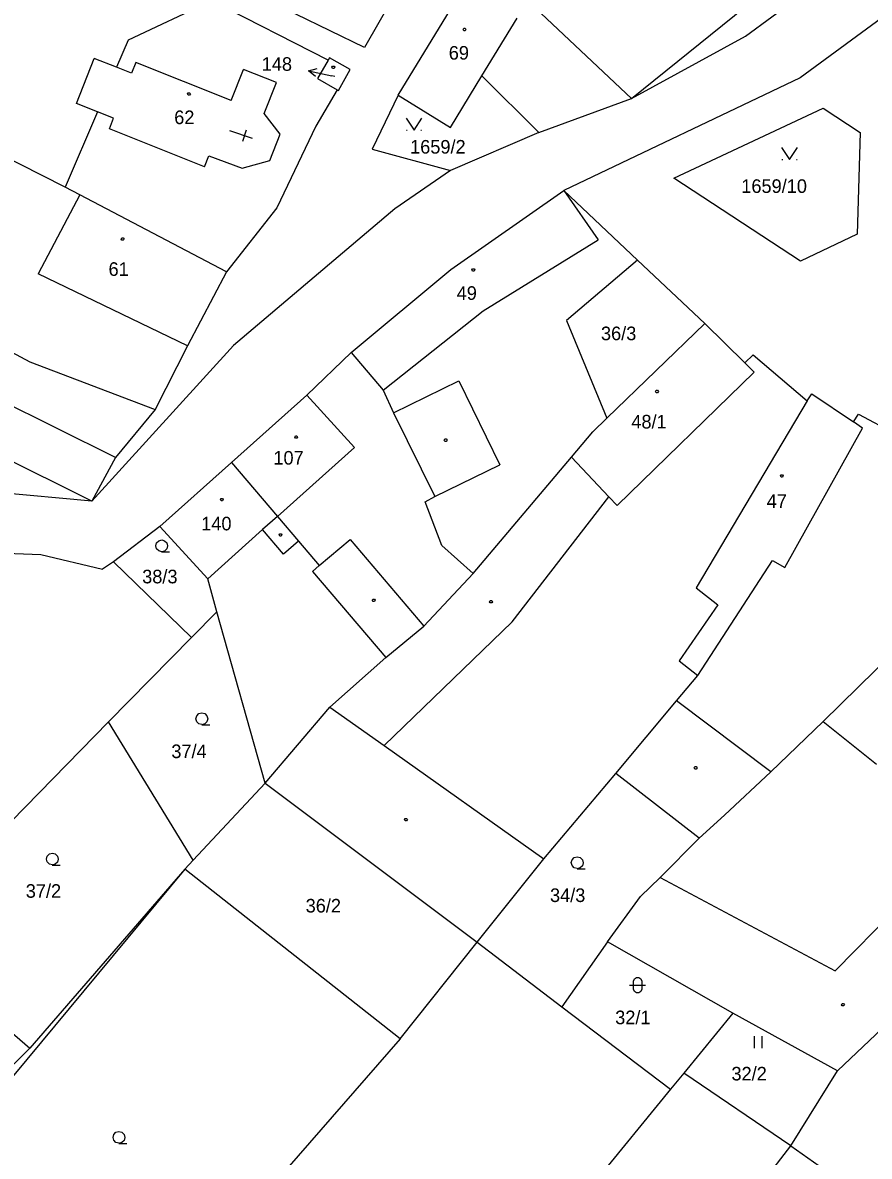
# Model space of a CAD drawing. Extents: x -802857 to -799647, y -1020285 to -1015884.
# Drawn here: x -801607.8 to -801501.8, y -1017782.1 to -1017640.2 of the extents above; entities that cross this region are included whole.
import ezdxf

# ---------------------------------------------------------------- set-up
doc = ezdxf.new("R2010")
doc.units = 0
for name, color, linetype in [('Default', 7, 'Continuous'), ('KN_HRANICE', 7, 'Continuous'), ('KN_KULTURY', 7, 'Continuous'), ('KN_PARCELY', 7, 'Continuous'), ('KN_SLUCKY', 7, 'Continuous')]:
    doc.layers.add(name, color=color, linetype=linetype)

# ---------------------------------------------------------------- blocks, each defined once
blk = doc.blocks.new('304')
at = {"layer": 'Default'}
blk.add_lwpolyline([(0, 0), (-0.38, 0.1), (-0.65, 0.37), (-0.75, 0.74), (-0.65, 1.11), (-0.38, 1.38), (-0.01, 1.48), (0.36, 1.38), (0.63, 1.11), (0.73, 0.73), (0.63, 0.35), (0.36, 0.08), (-0.02, -0.02), (0.98, -0.02)], dxfattribs=at)
blk = doc.blocks.new('306')
at = {"layer": 'Default'}
for p, q in [((-0.5, 1.5), (-0.5, 0)), ((0.5, 0), (0.5, 1.5))]:
    blk.add_line(p, q, dxfattribs=at)
blk = doc.blocks.new('314')
at = {"layer": 'Default'}
for p, q in [((-0.95, 0), (-0.85, 0)), ((0.85, 0), (0.95, 0))]:
    blk.add_line(p, q, dxfattribs=at)
blk.add_lwpolyline([(-1, 1.5), (0, 0), (1, 1.5)], dxfattribs=at)
blk = doc.blocks.new('316')
at = {"layer": 'Default'}
for points in [[(-0.5, 1.5), (-0.4, 1.79), (-0.15, 1.97), (0.16, 1.97), (0.41, 1.79), (0.51, 1.5), (0.51, 0.5), (0.41, 0.21), (0.16, 0.03), (-0.15, 0.03), (-0.4, 0.21), (-0.5, 0.5), (-0.5, 1.5)], [(-1, 1), (0.27, 1), (1, 1)]]:
    blk.add_lwpolyline(points, dxfattribs=at)
blk = doc.blocks.new('10292')
at = {"layer": 'Default'}
blk.add_line((0, 3), (0, 0), dxfattribs=at)
blk.add_lwpolyline([(-0.5, 2), (0, 3), (0.5, 2)], dxfattribs=at)
blk = doc.blocks.new('402')
at = {"layer": 'Default'}
blk.add_lwpolyline([(0.09, 0.15), (0.18, 0), (0.09, -0.15), (-0.09, -0.15), (-0.18, 0), (-0.09, 0.15), (0.09, 0.15)], dxfattribs=at)
blk = doc.blocks.new('4091')
at = {"layer": 'Default'}
for p, q in [((0, 0), (0, 3)), ((0.75, 2), (-0.75, 2))]:
    blk.add_line(p, q, dxfattribs=at)

msp = doc.modelspace()

# ---------------------------------------------------------------- linework, layer by layer
at = {"layer": 'KN_HRANICE'}
for p, q in [((-801531.59, -1017649.73), (-801511.2, -1017633.31)), ((-801565.01, -1017643.36), (-801583.43, -1017634.37)), ((-801560.01, -1017634.67), (-801565.01, -1017643.36)), ((-801547.58, -1017634.67), (-801531.59, -1017649.73)), ((-801560.79, -1017649.3), (-801552.43, -1017635.64)), ((-801517.33, -1017641.94), (-801509.19, -1017635.93)), ((-801584.1, -1017637.52), (-801594.58, -1017642.43)), ((-801569.55, -1017644.94), (-801584.1, -1017637.52)), ((-801499.03, -1017638.78), (-801510.49, -1017647.16)), ((-801531.59, -1017649.73), (-801517.33, -1017641.94)), ((-801594.58, -1017642.43), (-801596.03, -1017645.82)), ((-801601.05, -1017650.34), (-801598.81, -1017644.72)), ((-801596.03, -1017645.82), (-801598.81, -1017644.72)), ((-801569.37, -1017644.63), (-801569.55, -1017644.94)), ((-801566.77, -1017646.12), (-801569.37, -1017644.63)), ((-801569.55, -1017644.94), (-801570.87, -1017647.23)), ((-801568.27, -1017648.72), (-801566.77, -1017646.12)), ((-801570.87, -1017647.23), (-801568.42, -1017648.64)), ((-801554.25, -1017653.35), (-801550.3, -1017646.89)), ((-801543.18, -1017653.99), (-801550.3, -1017646.89)), ((-801510.49, -1017647.16), (-801540.03, -1017661.24)), ((-801568.42, -1017648.64), (-801571.07, -1017653.18)), ((-801568.42, -1017648.64), (-801568.27, -1017648.72)), ((-801598.41, -1017651.39), (-801601.05, -1017650.34)), ((-801560.79, -1017649.3), (-801564.03, -1017656.06)), ((-801560.79, -1017649.3), (-801554.25, -1017653.35)), ((-801543.18, -1017653.99), (-801531.59, -1017649.73)), ((-801598.41, -1017651.39), (-801602.44, -1017660.83)), ((-801526.27, -1017659.7), (-801507.58, -1017650.93)), ((-801507.58, -1017650.93), (-801502.97, -1017654)), ((-801571.07, -1017653.18), (-801575.98, -1017663.4)), ((-801543.18, -1017653.99), (-801554.23, -1017658.73)), ((-801502.97, -1017654), (-801503.35, -1017666.7)), ((-801602.44, -1017660.83), (-801613.19, -1017655.4)), ((-801564.03, -1017656.06), (-801554.23, -1017658.73)), ((-801554.23, -1017658.73), (-801561.22, -1017663.56)), ((-801510.43, -1017670.09), (-801526.27, -1017659.7)), ((-801600.62, -1017661.79), (-801602.44, -1017660.83)), ((-801582.26, -1017671.42), (-801600.62, -1017661.79)), ((-801554.18, -1017671.15), (-801540.03, -1017661.24)), ((-801540.03, -1017661.24), (-801530.82, -1017669.96)), ((-801575.98, -1017663.4), (-801582.26, -1017671.42)), ((-801561.22, -1017663.56), (-801581.38, -1017680.66)), ((-801503.35, -1017666.7), (-801510.43, -1017670.09)), ((-801632.7, -1017668.98), (-801606.86, -1017682.7)), ((-801530.82, -1017669.96), (-801539.73, -1017677.53)), ((-801530.82, -1017669.96), (-801522.42, -1017677.91)), ((-801582.26, -1017671.42), (-801587.15, -1017680.67)), ((-801566.65, -1017681.51), (-801554.18, -1017671.15)), ((-801539.73, -1017677.53), (-801534.65, -1017689.75)), ((-801534.65, -1017689.75), (-801522.42, -1017677.91)), ((-801522.42, -1017677.91), (-801517.41, -1017682.82)), ((-801581.38, -1017680.66), (-801599.1, -1017700.11)), ((-801587.15, -1017680.67), (-801591.2, -1017688.65)), ((-801572.23, -1017686.85), (-801566.65, -1017681.51)), ((-801566.65, -1017681.51), (-801562.64, -1017686.25)), ((-801606.86, -1017682.7), (-801591.2, -1017688.65)), ((-801517.41, -1017682.82), (-801516.36, -1017681.83)), ((-801516.36, -1017681.83), (-801509.58, -1017687.57)), ((-801581.65, -1017695.29), (-801572.23, -1017686.85)), ((-801562.64, -1017686.25), (-801561.35, -1017689.08)), ((-801509.58, -1017687.57), (-801509.03, -1017686.71)), ((-801509.03, -1017686.71), (-801503.79, -1017690.19)), ((-801591.2, -1017688.65), (-801596.17, -1017694.65)), ((-801509.58, -1017687.57), (-801523.48, -1017710.97)), ((-801561.35, -1017689.08), (-801556.21, -1017699.56)), ((-801536.4, -1017691.44), (-801534.65, -1017689.75)), ((-801503.79, -1017690.19), (-801503.16, -1017689.24)), ((-801503.16, -1017689.24), (-801493.48, -1017694.38)), ((-801539.1, -1017694.64), (-801536.4, -1017691.44)), ((-801596.17, -1017694.65), (-801599.1, -1017700.11)), ((-801590.59, -1017703.29), (-801581.65, -1017695.29)), ((-801581.65, -1017695.29), (-801575.88, -1017702.05)), ((-801551.39, -1017709.19), (-801539.1, -1017694.64)), ((-801599.1, -1017700.11), (-801612.31, -1017698.9)), ((-801557.41, -1017700.19), (-801556.21, -1017699.56)), ((-801555.3, -1017705.68), (-801557.41, -1017700.19)), ((-801575.88, -1017702.05), (-801573.25, -1017705.14)), ((-801590.59, -1017703.29), (-801596.4, -1017707.72)), ((-801584.61, -1017709.86), (-801590.59, -1017703.29)), ((-801573.25, -1017705.14), (-801570.66, -1017708.18)), ((-801551.39, -1017709.19), (-801555.3, -1017705.68)), ((-801614.64, -1017706.43), (-801605.52, -1017706.8)), ((-801605.52, -1017706.8), (-801597.79, -1017708.65)), ((-801596.4, -1017707.72), (-801597.79, -1017708.65)), ((-801586.66, -1017717.2), (-801596.4, -1017707.72)), ((-801570.66, -1017708.18), (-801571.51, -1017708.91)), ((-801583.46, -1017713.96), (-801584.61, -1017709.86)), ((-801571.51, -1017708.91), (-801562.32, -1017719.68)), ((-801557.56, -1017715.75), (-801551.39, -1017709.19)), ((-801523.48, -1017710.97), (-801520.79, -1017713.1)), ((-801583.46, -1017713.96), (-801586.66, -1017717.2)), ((-801577.44, -1017735.41), (-801583.46, -1017713.96)), ((-801520.79, -1017713.1), (-801525.6, -1017720.1)), ((-801562.32, -1017719.68), (-801557.56, -1017715.75)), ((-801586.66, -1017717.2), (-801597.05, -1017727.73)), ((-801569.32, -1017725.92), (-801562.32, -1017719.68)), ((-801498.85, -1017719.1), (-801507.61, -1017727.7)), ((-801525.6, -1017720.1), (-801523.26, -1017721.95)), ((-801525.93, -1017725.13), (-801523.26, -1017721.95)), ((-801533.55, -1017734.19), (-801525.93, -1017725.13)), ((-801577.44, -1017735.41), (-801569.32, -1017725.92)), ((-801597.05, -1017727.73), (-801623.18, -1017754.46)), ((-801586.42, -1017745.04), (-801597.05, -1017727.73)), ((-801507.61, -1017727.7), (-801514.13, -1017733.99)), ((-801542.55, -1017744.89), (-801533.55, -1017734.19)), ((-801523.13, -1017742.28), (-801533.55, -1017734.19)), ((-801514.13, -1017733.99), (-801519.94, -1017739.41)), ((-801586.42, -1017745.04), (-801577.44, -1017735.41)), ((-801577.44, -1017735.41), (-801550.9, -1017755.33)), ((-801519.94, -1017739.41), (-801523.13, -1017742.28)), ((-801523.13, -1017742.28), (-801527.98, -1017747.21)), ((-801587.49, -1017746.18), (-801586.42, -1017745.04)), ((-801550.9, -1017755.33), (-801542.55, -1017744.89)), ((-801587.49, -1017746.18), (-801629.02, -1017796.14)), ((-801587.49, -1017746.18), (-801606.88, -1017768.59)), ((-801560.55, -1017767.41), (-801587.49, -1017746.18)), ((-801530.45, -1017749.6), (-801527.98, -1017747.21)), ((-801534.59, -1017755.26), (-801530.45, -1017749.6)), ((-801623.18, -1017754.46), (-801606.88, -1017768.59)), ((-801560.55, -1017767.41), (-801550.9, -1017755.33)), ((-801550.9, -1017755.33), (-801540.28, -1017763.4)), ((-801534.59, -1017755.26), (-801540.28, -1017763.4)), ((-801518.91, -1017764.22), (-801534.59, -1017755.26)), ((-801540.28, -1017763.4), (-801526.7, -1017773.73)), ((-801518.91, -1017764.22), (-801525.04, -1017771.7)), ((-801505.81, -1017771.41), (-801518.91, -1017764.22)), ((-801498.56, -1017764.53), (-801505.81, -1017771.41)), ((-801560.55, -1017767.41), (-801606.93, -1017820.56)), ((-801606.88, -1017768.59), (-801631.76, -1017793.06)), ((-801525.04, -1017771.7), (-801526.7, -1017773.73)), ((-801511.62, -1017780.82), (-801525.04, -1017771.7)), ((-801511.62, -1017780.82), (-801505.81, -1017771.41)), ((-801526.7, -1017773.73), (-801584.65, -1017844.45)), ((-801515.62, -1017785.98), (-801511.62, -1017780.82)), ((-801511.62, -1017780.82), (-801502.15, -1017787.45))]:
    msp.add_line(p, q, dxfattribs=at)
at = {"layer": 'KN_PARCELY'}
msp.add_line((-801568.7, -1017646.97), (-801569.07, -1017646.89), dxfattribs=at)
at = {"layer": 'KN_SLUCKY'}
for p, q in [((-801550.3, -1017646.89), (-801545.89, -1017639.69)), ((-801594.15, -1017646.57), (-801596.03, -1017645.82)), ((-801593.62, -1017645.23), (-801594.15, -1017646.57)), ((-801581.7, -1017649.97), (-801593.62, -1017645.23)), ((-801581.7, -1017649.97), (-801580.15, -1017646.09)), ((-801576.01, -1017647.74), (-801580.15, -1017646.09)), ((-801577.55, -1017651.62), (-801576.01, -1017647.74)), ((-801596.39, -1017652.19), (-801598.41, -1017651.39)), ((-801575.55, -1017654.18), (-801577.55, -1017651.62)), ((-801596.92, -1017653.53), (-801596.39, -1017652.19)), ((-801585, -1017658.27), (-801596.92, -1017653.53)), ((-801576.85, -1017657.48), (-801575.55, -1017654.18)), ((-801585, -1017658.27), (-801584.47, -1017656.93)), ((-801584.47, -1017656.93), (-801580.31, -1017658.44)), ((-801580.31, -1017658.44), (-801576.85, -1017657.48)), ((-801600.62, -1017661.79), (-801605.85, -1017671.68)), ((-801540.03, -1017661.24), (-801535.75, -1017667.43)), ((-801550.14, -1017676.32), (-801535.75, -1017667.43)), ((-801587.15, -1017680.67), (-801605.85, -1017671.68)), ((-801562.64, -1017686.25), (-801550.14, -1017676.32)), ((-801596.17, -1017694.65), (-801621.15, -1017682.25)), ((-801517.41, -1017682.82), (-801516.21, -1017684)), ((-801516.21, -1017684), (-801533.38, -1017700.68)), ((-801561.35, -1017689.08), (-801553.2, -1017685.08)), ((-801553.2, -1017685.08), (-801548.06, -1017695.56)), ((-801572.23, -1017686.85), (-801566.24, -1017693.43)), ((-801502.65, -1017691), (-801503.79, -1017690.19)), ((-801512.41, -1017708.44), (-801502.65, -1017691)), ((-801599.1, -1017700.11), (-801612.74, -1017693.34)), ((-801566.24, -1017693.43), (-801575.88, -1017702.05)), ((-801556.21, -1017699.56), (-801548.06, -1017695.56)), ((-801534.43, -1017699.57), (-801539.1, -1017694.64)), ((-801546.51, -1017715.23), (-801534.43, -1017699.57)), ((-801533.38, -1017700.68), (-801534.43, -1017699.57)), ((-801575.88, -1017702.05), (-801577.78, -1017703.68)), ((-801577.78, -1017703.68), (-801584.61, -1017709.86)), ((-801575.14, -1017706.75), (-801577.78, -1017703.68)), ((-801573.25, -1017705.14), (-801575.14, -1017706.75)), ((-801570.66, -1017708.18), (-801566.79, -1017704.93)), ((-801566.79, -1017704.93), (-801557.56, -1017715.75)), ((-801523.26, -1017721.95), (-801513.92, -1017707.57)), ((-801513.92, -1017707.57), (-801512.41, -1017708.44)), ((-801546.51, -1017715.23), (-801562.54, -1017730.72)), ((-801514.13, -1017733.99), (-801525.93, -1017725.13)), ((-801569.32, -1017725.92), (-801562.54, -1017730.72)), ((-801507.61, -1017727.7), (-801500.92, -1017733.04)), ((-801562.54, -1017730.72), (-801542.55, -1017744.89)), ((-801506.09, -1017758.92), (-801488.83, -1017741.31)), ((-801527.98, -1017747.21), (-801506.09, -1017758.92))]:
    msp.add_line(p, q, dxfattribs=at)

# ---------------------------------------------------------------- block references
at = {"layer": 'KN_KULTURY'}
for name, p in [('402', (-801552.48, -1017641.1)), ('402', (-801568.9, -1017645.82)), ('402', (-801586.97, -1017649.17)), ('314', (-801558.8, -1017653.7)), ('314', (-801511.8, -1017657.36)), ('402', (-801595.27, -1017667.33)), ('402', (-801551.38, -1017671.19)), ('402', (-801528.4, -1017686.4)), ('402', (-801573.54, -1017692.1)), ('402', (-801554.85, -1017692.49)), ('402', (-801512.76, -1017696.96)), ('402', (-801582.85, -1017699.93)), ('402', (-801575.51, -1017704.35)), ('304', (-801590.37, -1017706.45)), ('402', (-801563.84, -1017712.53)), ('402', (-801549.16, -1017712.71)), ('304', (-801585.34, -1017728.09)), ('402', (-801523.56, -1017733.5)), ('402', (-801559.81, -1017739.98)), ('304', (-801604.05, -1017745.65)), ('304', (-801538.36, -1017746.1)), ('316', (-801530.81, -1017761.69)), ('402', (-801505.12, -1017763.14)), ('306', (-801515.73, -1017768.58)), ('304', (-801595.72, -1017780.48))]:
    msp.add_blockref(name, p, dxfattribs=at)
at = {"layer": 'KN_KULTURY', "rotation": -108.52882400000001}
msp.add_blockref('4091', (-801581.89, -1017653.73), dxfattribs=at)
at = {"layer": 'KN_PARCELY', "rotation": 78.036852}
msp.add_blockref('10292', (-801569.07, -1017646.89), dxfattribs=at)

# ---------------------------------------------------------------- texts
at = {"layer": 'KN_PARCELY'}
for s, height, p in [('69', 1.7, (-801554.45, -1017644.87)), ('148', 1.7, (-801577.86, -1017646.27)), ('148', 0.1, (-801568.85, -1017646.97)), ('62', 1.7, (-801588.81, -1017652.94)), ('1659/2', 1.7, (-801559.29, -1017656.63)), ('1659/10', 1.7, (-801517.84, -1017661.55)), ('61', 1.7, (-801597.03, -1017671.93)), ('49', 1.7, (-801553.46, -1017674.93)), ('36/3', 1.7, (-801535.4, -1017679.98)), ('48/1', 1.7, (-801531.6, -1017691.03)), ('107', 1.7, (-801576.4, -1017695.55)), ('47', 1.7, (-801514.66, -1017700.97)), ('140', 1.7, (-801585.43, -1017703.78)), ('38/3', 1.7, (-801592.82, -1017710.41)), ('37/4', 1.7, (-801589.17, -1017732.28)), ('37/2', 1.7, (-801607.39, -1017749.76)), ('36/2', 1.7, (-801572.36, -1017751.6)), ('34/3', 1.7, (-801541.78, -1017750.29)), ('32/1', 1.7, (-801533.62, -1017765.58)), ('32/2', 1.7, (-801519.07, -1017772.62))]:
    msp.add_text(s, height=height, dxfattribs=at).set_placement(p)

doc.saveas('drawing.dxf')
